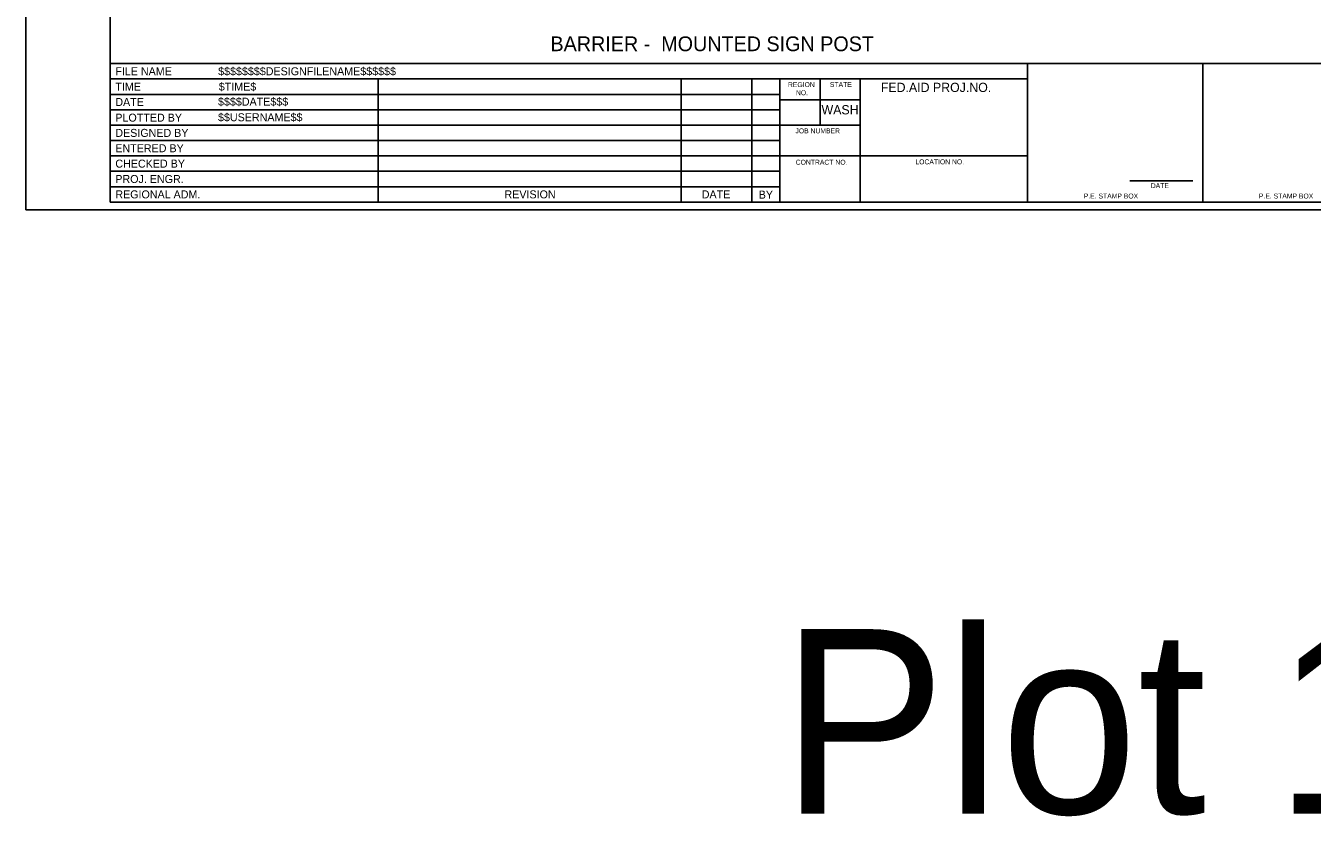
# Model space of a CAD drawing. Extents: x 99988 to 100172, y 99995 to 100047.
# Drawn here: x 99999.31 to 100009.77, y 99995.01 to 100001.43 of the extents above; entities that cross this region are included whole.
import ezdxf

# ---------------------------------------------------------------- set-up
doc = ezdxf.new("R2010")
doc.units = 0
for name, color, linetype in [('Level 20', 7, 'Continuous'), ('SH_GI_PlotLimits', 7, 'Continuous'), ('SH_GI_SheetBorder', 7, 'Continuous'), ('SH_GI_SheetLocationText', 7, 'Continuous'), ('SH_GI_SheetTextInCells', 7, 'Continuous'), ('SH_GI_TitleBlockText', 7, 'Continuous')]:
    doc.layers.add(name, color=color, linetype=linetype)

msp = doc.modelspace()

# ---------------------------------------------------------------- linework, layer by layer
at = {"layer": 'SH_GI_PlotLimits'}
msp.add_lwpolyline([(99999.312, 99999.937), (100015.812, 99999.937), (100015.812, 100010.437), (99999.312, 100010.437)], close=True, dxfattribs=at)
at = {"layer": 'SH_GI_SheetBorder'}
for p, q in [((100000, 100010.375), (100000, 100000)), ((100000, 100001.126), (100015.75, 100001.126)), ((100007.457, 100000), (100007.457, 100001.126)), ((100008.883, 100000), (100008.883, 100001.126)), ((100000, 100001.001), (100007.457, 100001.001)), ((100002.179, 100001.001), (100002.179, 100000)), ((100004.641, 100001.001), (100004.641, 100000)), ((100005.216, 100001.001), (100005.216, 100000)), ((100005.445, 100001.001), (100005.445, 100000)), ((100005.772, 100000.625), (100005.772, 100001.001)), ((100006.096, 100000), (100006.096, 100001.001)), ((100000, 100000.876), (100002.182, 100000.876)), ((100002.182, 100000.876), (100005.447, 100000.876)), ((100006.096, 100000.831), (100005.447, 100000.831)), ((100000, 100000.751), (100002.182, 100000.751)), ((100002.182, 100000.751), (100005.447, 100000.751)), ((100000, 100000.625), (100005.447, 100000.625)), ((100006.096, 100000.625), (100005.447, 100000.625)), ((100000, 100000.5), (100005.447, 100000.5)), ((100000, 100000.375), (100005.447, 100000.375)), ((100007.457, 100000.375), (100005.447, 100000.375)), ((100000, 100000.25), (100005.447, 100000.25)), ((100008.29, 100000.173), (100008.802, 100000.173)), ((100000, 100000.125), (100005.447, 100000.125)), ((100000, 100000), (100015.75, 100000))]:
    msp.add_line(p, q, dxfattribs=at)

# ---------------------------------------------------------------- texts
at = {"layer": 'Level 20'}
msp.add_text('BARRIER -  MOUNTED SIGN POST', height=0.12, dxfattribs=at).set_placement((100003.579, 100001.227))
at = {"layer": 'SH_GI_SheetLocationText'}
msp.add_text('Plot 1', height=1.5, dxfattribs=at).set_placement((100005.455, 99995.027))
at = {"layer": 'SH_GI_SheetTextInCells'}
for s, height, p in [('FILE NAME', 0.0651, (100000.041, 100001.031)), ('TIME', 0.0651, (100000.041, 100000.906)), ('REGION', 0.04, (100005.51, 100000.935)), ('NO.', 0.04, (100005.575, 100000.869)), ('STATE', 0.04, (100005.851, 100000.936)), ('FED.AID PROJ.NO.', 0.07506, (100006.265, 100000.895)), ('DATE', 0.0651, (100000.041, 100000.781)), ('WASH', 0.0751, (100005.783, 100000.713)), ('PLOTTED BY', 0.0651, (100000.041, 100000.654)), ('DESIGNED BY', 0.06505, (100000.041, 100000.53)), ('JOB NUMBER', 0.04, (100005.571, 100000.559)), ('ENTERED BY', 0.0651, (100000.041, 100000.405)), ('CHECKED BY', 0.0651, (100000.041, 100000.28)), ('CONTRACT NO.', 0.04003, (100005.573, 100000.304)), ('LOCATION NO.', 0.04003, (100006.546, 100000.307)), ('PROJ. ENGR.', 0.06505, (100000.041, 100000.155)), ('DATE', 0.04, (100008.46, 100000.114)), ('REGIONAL ADM.', 0.06505, (100000.041, 100000.03)), ('REVISION', 0.0651, (100003.205, 100000.03)), ('DATE', 0.0651, (100004.809, 100000.03)), ('BY', 0.0651, (100005.272, 100000.028)), ('P.E. STAMP BOX', 0.04003, (100007.915, 100000.029)), ('P.E. STAMP BOX', 0.04003, (100009.339, 100000.029))]:
    msp.add_text(s, height=height, dxfattribs=at).set_placement(p)
at = {"layer": 'SH_GI_TitleBlockText'}
for s, height, p in [('$$$$$$$$DESIGNFILENAME$$$$$$', 0.06505, (100000.877, 100001.031)), ('$TIME$', 0.0651, (100000.882, 100000.906)), ('$$$$DATE$$$', 0.06505, (100000.876, 100000.784)), ('$$USERNAME$$', 0.06505, (100000.876, 100000.657))]:
    msp.add_text(s, height=height, dxfattribs=at).set_placement(p)

doc.saveas('drawing.dxf')
